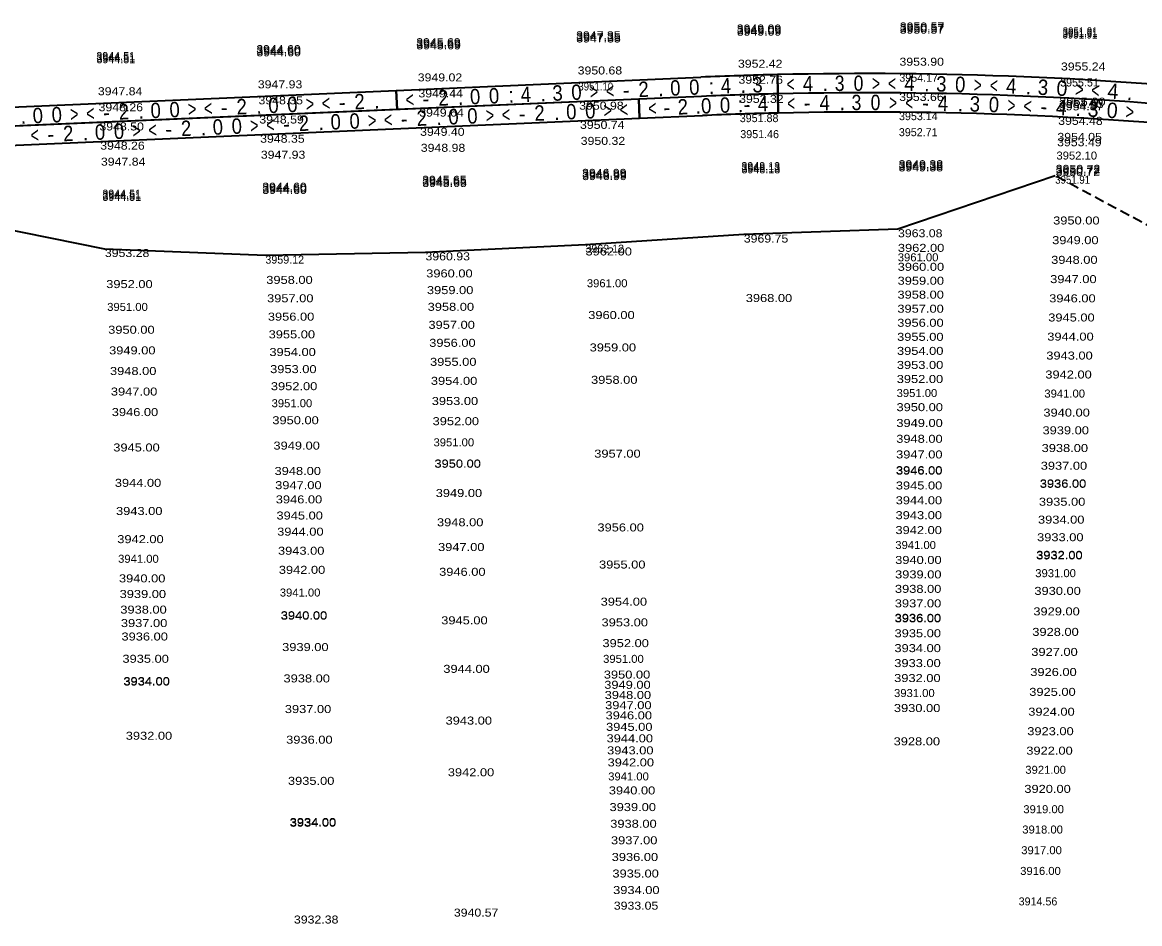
# Model space of a CAD drawing. Extents: x 49942 to 56479, y 47140 to 53283.
# Drawn here: x 53343 to 54041, y 49300 to 49863 of the extents above; entities that cross this region are included whole.
import ezdxf
from ezdxf.enums import TextEntityAlignment as Align

# ---------------------------------------------------------------- set-up
doc = ezdxf.new("R2010")
doc.units = 0
doc.header["$LTSCALE"] = 2
doc.linetypes.add('MEDIUM_DASHED', pattern=[4.5, 3, -1.5])
doc.layers.add('29', color=7, linetype='Continuous')
doc.layers.add('59', color=7, linetype='Continuous', lineweight=35)
doc.layers.add('63', color=7, linetype='Continuous', lineweight=35)

msp = doc.modelspace()

# ---------------------------------------------------------------- linework, layer by layer
at = {"layer": '59'}
for p, q in [((53988.534, 49767.027), (53890.322, 49733.603)), ((53394.861, 49721.266), (53293.897, 49741.36)), ((53890.322, 49733.603), (53793.986, 49730.281)), ((53695.025, 49723.963), (53595.139, 49719.179)), ((53793.986, 49730.281), (53695.025, 49723.963)), ((53495.134, 49717.131), (53394.861, 49721.266)), ((53595.139, 49719.179), (53495.134, 49717.131))]:
    msp.add_line(p, q, dxfattribs=at)
at = {"layer": '59', "linetype": 'MEDIUM_DASHED'}
msp.add_line((54082.2, 49716.709), (53988.534, 49767.027), dxfattribs=at)
at = {"layer": '63'}
for p, q in [((53576.866, 49820.33), (53767.149, 49828.569)), ((53814.981, 49830.161), (53815.26, 49818.164)), ((53815.26, 49818.164), (53814.981, 49830.161)), ((53815.539, 49806.167), (53815.26, 49818.164)), ((53815.26, 49818.164), (53815.539, 49806.167)), ((53728.923, 49802.891), (53768.187, 49804.591))]:
    msp.add_line(p, q, dxfattribs=at)
for points in [[(52494.091, 49773.45), (53576.866, 49820.33), (53577.385, 49808.342), (52494.61, 49761.461)], [(52680.665, 49757.505), (53728.923, 49802.891), (53728.404, 49814.88), (52680.146, 49769.494)]]:
    msp.add_lwpolyline(points, close=True, dxfattribs=at)
for points in [[(53767.668, 49816.58), (53577.385, 49808.342), (53576.866, 49820.33)], [(53767.668, 49816.58), (53728.404, 49814.88), (53728.923, 49802.891)]]:
    msp.add_lwpolyline(points, dxfattribs=at)
for radius, start, end in [(2391.064, 91.33234, 92.47917), (2391.064, 76.58708, 91.33234), (2379.064, 91.33234, 92.47917), (2379.064, 91.33234, 92.47917), (2379.064, 76.58708, 91.33234), (2379.064, 76.58708, 91.33234), (2367.064, 91.33234, 92.47917), (2367.064, 76.58708, 91.33234)]:
    msp.add_arc((53870.577, 47439.743), radius, start, end, dxfattribs=at)

# ---------------------------------------------------------------- texts
at = {"layer": '29'}
for s, width, p in [('3947.35', 1.15, (53689.256, 49852.226)), ('3949.09', 1.15, (53789.599, 49856.453)), ('3949.09', 1.15, (53789.633, 49855.454)), ('3949.09', 1.15, (53789.666, 49854.454)), ('3950.57', 1.15, (53891.416, 49855.717)), ('3950.57', 1.15, (53891.425, 49856.717)), ('3950.57', 1.15, (53891.434, 49857.717)), ('3951.91', 0.9, (53993.13, 49852.703)), ('3951.91', 0.9, (53993.18, 49853.702)), ('3951.91', 0.9, (53993.231, 49854.7)), ('3945.69', 1.15, (53589.349, 49847.901)), ('3945.69', 1.15, (53589.393, 49846.902)), ('3945.69', 1.15, (53589.436, 49845.903)), ('3947.35', 1.15, (53689.299, 49851.227)), ('3947.35', 1.15, (53689.342, 49850.228)), ('3944.60', 1.15, (53489.443, 49843.575)), ('3944.60', 1.15, (53489.486, 49842.576)), ('3944.60', 1.15, (53489.529, 49841.577)), ('3952.42', 1.15, (53790.335, 49834.466)), ('3953.90', 1.15, (53891.244, 49835.718)), ('3955.24', 1.15, (53992.117, 49832.729)), ('3949.02', 1.15, (53590.301, 49825.921)), ('3950.68', 1.15, (53690.207, 49830.247)), ('3952.76', 1.15, (53790.669, 49824.471)), ('3947.84', 1.15, (53390.488, 49817.27)), ('3947.93', 1.15, (53490.395, 49821.596)), ('3951.10', 0.9, (53690.64, 49820.256)), ('3948.35', 1.15, (53490.827, 49811.605)), ('3949.44', 1.15, (53590.733, 49815.931)), ('3952.32', 1.15, (53791.07, 49812.478)), ('3953.66', 1.15, (53891.055, 49813.719)), ('3955.00', 1.2, (53991.004, 49810.757)), ('3948.26', 1.15, (53390.921, 49807.279)), ('3949.64', 1.15, (53591.253, 49803.942)), ('3950.98', 1.15, (53691.159, 49808.267)), ('3954.87', 1.15, (53990.855, 49807.815)), ('3954.93', 1.15, (53990.929, 49809.286)), ('3948.59', 1.15, (53491.346, 49799.616)), ('3950.74', 1.15, (53691.678, 49796.279)), ('3954.48', 1.15, (53990.396, 49798.772)), ('3948.50', 1.15, (53391.44, 49795.291)), ('3949.40', 1.15, (53591.772, 49791.953)), ('3954.05', 1.15, (53989.89, 49788.785)), ('3948.26', 1.15, (53391.959, 49783.302)), ('3948.35', 1.15, (53491.865, 49787.627)), ('3948.98', 1.15, (53592.204, 49781.963)), ('3950.32', 1.15, (53692.111, 49786.288)), ('3953.49', 1.15, (53989.719, 49785.415)), ('3947.93', 1.15, (53492.298, 49777.637)), ('3952.10', 1.05, (53989.298, 49777.113)), ('3947.84', 1.15, (53392.391, 49773.311)), ('3949.38', 1.15, (53890.676, 49769.72)), ('3949.38', 1.15, (53890.685, 49770.72)), ('3949.38', 1.15, (53890.693, 49771.72)), ('3950.72', 1.15, (53988.827, 49767.812)), ('3950.72', 1.15, (53988.878, 49768.811)), ('3945.65', 1.15, (53593.069, 49761.981)), ('3945.65', 1.15, (53593.112, 49760.982)), ('3946.99', 1.15, (53692.976, 49766.307)), ('3946.99', 1.15, (53693.019, 49765.308)), ('3946.99', 1.15, (53693.062, 49764.309)), ('3951.91', 0.9, (53988.534, 49762.027)), ('3950.72', 1.15, (53988.776, 49766.813)), ('3944.60', 1.15, (53493.163, 49757.656)), ('3944.60', 1.15, (53493.206, 49756.657)), ('3944.60', 1.15, (53493.249, 49755.657)), ('3945.65', 1.15, (53593.156, 49759.983)), ('3950.00', 1.2, (53987.244, 49736.577)), ('3963.08', 1.15, (53890.322, 49728.603)), ('3969.75', 1.15, (53793.986, 49725.282)), ('3962.00', 1.2, (53890.244, 49719.477)), ('3949.00', 1.2, (53986.621, 49724.288)), ('3953.28', 1.15, (53394.861, 49716.266)), ('3960.93', 1.15, (53595.139, 49714.179)), ('3962.00', 1.2, (53695.1, 49717.235)), ('3961.00', 1.05, (53890.193, 49713.579)), ('3948.00', 1.2, (53985.998, 49711.998)), ('3960.00', 1.2, (53890.142, 49707.647)), ('3958.00', 1.2, (53495.682, 49699.472)), ('3960.00', 1.2, (53595.6, 49703.531)), ('3959.00', 1.2, (53890.067, 49698.961)), ('3947.00', 1.2, (53985.389, 49699.975)), ('3952.00', 1.2, (53395.701, 49696.867)), ('3959.00', 1.2, (53596.051, 49693.103)), ('3961.00', 1.05, (53695.96, 49697.385)), ('3957.00', 1.2, (53496.179, 49688.002)), ('3968.00', 1.2, (53795.227, 49688.15)), ('3958.00', 1.2, (53889.992, 49690.275)), ('3946.00', 1.2, (53984.779, 49687.953)), ('3951.00', 1.05, (53396.319, 49682.608)), ('3958.00', 1.2, (53596.503, 49682.675)), ('3960.00', 1.2, (53696.819, 49677.535)), ('3957.00', 1.2, (53889.917, 49681.491)), ('3956.00', 1.2, (53496.675, 49676.531)), ('3957.00', 1.2, (53596.99, 49671.43)), ('3956.00', 1.2, (53889.841, 49672.708)), ('3945.00', 1.2, (53984.174, 49676.01)), ('3950.00', 1.2, (53396.936, 49668.349)), ('3955.00', 1.2, (53497.154, 49665.484)), ('3955.00', 1.2, (53889.766, 49663.928)), ('3944.00', 1.2, (53983.569, 49664.068)), ('3956.00', 1.2, (53597.477, 49660.185)), ('3959.00', 1.2, (53697.695, 49657.307)), ('3949.00', 1.2, (53397.494, 49655.469)), ('3954.00', 1.2, (53497.632, 49654.438)), ('3954.00', 1.2, (53889.69, 49655.147)), ('3943.00', 1.2, (53982.969, 49652.234)), ('3948.00', 1.2, (53398.051, 49642.59)), ('3953.00', 1.2, (53498.094, 49643.77)), ('3955.00', 1.2, (53597.991, 49648.317)), ('3953.00', 1.2, (53889.614, 49646.378)), ('3954.00', 1.2, (53598.504, 49636.449)), ('3958.00', 1.2, (53698.571, 49637.08)), ('3952.00', 1.2, (53889.539, 49637.608)), ('3942.00', 1.2, (53982.369, 49640.399)), ('3947.00', 1.2, (53398.606, 49629.764)), ('3952.00', 1.2, (53498.556, 49633.101)), ('3951.00', 1.05, (53889.463, 49628.833)), ('3941.00', 1.05, (53981.767, 49628.512)), ('3951.00', 1.05, (53499.016, 49622.474)), ('3953.00', 1.2, (53599.05, 49623.856)), ('3946.00', 1.2, (53399.162, 49616.939)), ('3950.00', 1.2, (53889.387, 49620.008)), ('3940.00', 1.2, (53981.164, 49616.624)), ('3950.00', 1.2, (53499.476, 49611.847)), ('3952.00', 1.2, (53599.595, 49611.262)), ('3949.00', 1.2, (53889.302, 49610.133)), ('3948.00', 1.2, (53889.217, 49600.259)), ('3939.00', 1.2, (53980.603, 49605.551)), ('3945.00', 1.2, (53400.118, 49594.849)), ('3949.00', 1.2, (53500.162, 49596.01)), ('3951.00', 1.05, (53600.167, 49598.053)), ('3938.00', 1.2, (53980.042, 49594.478)), ('3957.00', 1.2, (53700.566, 49590.994)), ('3947.00', 1.2, (53889.133, 49590.494)), ('3948.00', 1.2, (53500.847, 49580.173)), ('3950.00', 1.2, (53600.739, 49584.844)), ('3950.00', 1.2, (53600.742, 49584.761)), ('3950.00', 1.2, (53600.747, 49584.664)), ('3946.00', 1.2, (53889.046, 49580.363)), ('3946.00', 1.2, (53889.048, 49580.527)), ('3946.00', 1.2, (53889.049, 49580.691)), ('3937.00', 1.2, (53979.483, 49583.445)), ('3944.00', 1.2, (53401.075, 49572.758)), ('3936.00', 1.2, (53978.916, 49572.275)), ('3936.00', 1.2, (53978.923, 49572.413)), ('3947.00', 1.2, (53501.231, 49571.301)), ('3949.00', 1.2, (53601.537, 49566.398)), ('3945.00', 1.2, (53888.967, 49571.116)), ('3936.00', 1.2, (53978.909, 49572.133)), ('3946.00', 1.2, (53501.616, 49562.428)), ('3944.00', 1.2, (53888.887, 49561.868)), ('3935.00', 1.2, (53978.343, 49560.96)), ('3943.00', 1.2, (53401.836, 49555.176)), ('3945.00', 1.2, (53502.052, 49552.355)), ('3943.00', 1.2, (53888.807, 49552.565)), ('3948.00', 1.2, (53602.328, 49548.133)), ('3956.00', 1.2, (53702.562, 49544.907)), ('3934.00', 1.2, (53977.776, 49549.786)), ('3942.00', 1.2, (53402.597, 49537.594)), ('3944.00', 1.2, (53502.488, 49542.282)), ('3942.00', 1.2, (53888.727, 49543.262)), ('3933.00', 1.2, (53977.219, 49538.794)), ('3943.00', 1.2, (53503.004, 49530.359)), ('3947.00', 1.2, (53602.998, 49532.669)), ('3941.00', 1.05, (53888.647, 49533.936)), ('3941.00', 1.05, (53403.128, 49525.344)), ('3940.00', 1.2, (53888.566, 49524.61)), ('3932.00', 1.2, (53976.643, 49527.425)), ('3932.00', 1.2, (53976.653, 49527.623)), ('3932.00', 1.2, (53976.662, 49527.802)), ('3942.00', 1.2, (53503.52, 49518.437)), ('3946.00', 1.2, (53603.667, 49517.204)), ('3955.00', 1.2, (53703.565, 49521.743)), ('3931.00', 1.05, (53976.082, 49516.355)), ('3940.00', 1.2, (53403.658, 49513.093)), ('3939.00', 1.2, (53888.488, 49515.583)), ('3939.00', 1.2, (53404.08, 49503.345)), ('3941.00', 1.05, (53504.134, 49504.269)), ('3938.00', 1.2, (53888.411, 49506.555)), ('3930.00', 1.2, (53975.521, 49505.285)), ('3954.00', 1.2, (53704.567, 49498.577)), ('3937.00', 1.2, (53888.333, 49497.514)), ('3938.00', 1.2, (53404.502, 49493.597)), ('3940.00', 1.2, (53504.747, 49490.101)), ('3940.00', 1.2, (53504.752, 49489.98)), ('3940.00', 1.2, (53504.761, 49489.789)), ('3936.00', 1.2, (53888.255, 49488.472)), ('3929.00', 1.2, (53974.872, 49492.489)), ('3937.00', 1.2, (53404.866, 49485.198)), ('3945.00', 1.2, (53604.979, 49486.903)), ('3953.00', 1.2, (53705.128, 49485.62)), ('3936.00', 1.2, (53888.252, 49488.123)), ('3936.00', 1.2, (53888.254, 49488.3)), ('3936.00', 1.2, (53405.229, 49476.798)), ('3935.00', 1.2, (53888.172, 49478.839)), ('3928.00', 1.2, (53974.224, 49479.694)), ('3939.00', 1.2, (53505.608, 49470.21)), ('3952.00', 1.2, (53705.689, 49472.663)), ('3934.00', 1.2, (53888.092, 49469.554)), ('3935.00', 1.2, (53405.831, 49462.896)), ('3951.00', 1.05, (53706.114, 49462.849)), ('3927.00', 1.2, (53973.59, 49467.185)), ('3944.00', 1.2, (53606.291, 49456.601)), ('3933.00', 1.2, (53888.012, 49460.207)), ('3926.00', 1.2, (53972.954, 49454.633)), ('3934.00', 1.2, (53406.433, 49448.995)), ('3934.00', 1.2, (53406.441, 49448.825)), ('3934.00', 1.2, (53406.448, 49448.655)), ('3938.00', 1.2, (53506.456, 49450.631)), ('3950.00', 1.2, (53706.539, 49453.035)), ('3949.00', 1.2, (53706.815, 49446.665)), ('3932.00', 1.2, (53887.931, 49450.861)), ('3948.00', 1.2, (53707.091, 49440.295)), ('3931.00', 1.05, (53887.851, 49441.497)), ('3925.00', 1.2, (53972.325, 49442.238)), ('3947.00', 1.2, (53707.366, 49433.931)), ('3937.00', 1.2, (53507.284, 49431.499)), ('3946.00', 1.2, (53707.642, 49427.566)), ('3930.00', 1.2, (53887.77, 49432.132)), ('3924.00', 1.2, (53971.697, 49429.843)), ('3943.00', 1.2, (53607.689, 49424.316)), ('3945.00', 1.2, (53707.953, 49420.395)), ('3932.00', 1.2, (53407.912, 49414.832)), ('3936.00', 1.2, (53508.113, 49412.368)), ('3944.00', 1.2, (53708.263, 49413.224)), ('3923.00', 1.2, (53971.081, 49417.679)), ('3943.00', 1.2, (53708.588, 49405.709)), ('3928.00', 1.2, (53887.591, 49411.347)), ('3922.00', 1.2, (53970.464, 49405.515)), ('3942.00', 1.2, (53708.914, 49398.194)), ('3942.00', 1.2, (53609.087, 49392.031)), ('3921.00', 1.05, (53969.86, 49393.586)), ('3935.00', 1.2, (53509.225, 49386.682)), ('3941.00', 1.05, (53709.293, 49389.443)), ('3940.00', 1.2, (53709.671, 49380.693)), ('3920.00', 1.2, (53969.255, 49381.657)), ('3939.00', 1.2, (53710.122, 49370.292)), ('3919.00', 1.05, (53968.612, 49368.967)), ('3934.00', 1.2, (53510.337, 49360.997)), ('3934.00', 1.2, (53510.346, 49360.795)), ('3934.00', 1.2, (53510.358, 49360.509)), ('3938.00', 1.2, (53710.572, 49359.89)), ('3918.00', 1.05, (53967.969, 49356.278)), ('3937.00', 1.2, (53711.019, 49349.559)), ('3917.00', 1.05, (53967.314, 49343.357)), ('3936.00', 1.2, (53711.471, 49339.132)), ('3935.00', 1.2, (53711.918, 49328.81)), ('3916.00', 1.05, (53966.659, 49330.436)), ('3934.00', 1.2, (53712.365, 49318.489)), ('3933.05', 1.15, (53712.787, 49308.736)), ('3932.38', 1.15, (53512.974, 49300.084)), ('3940.57', 1.15, (53612.881, 49304.41))]:
    msp.add_text(s, height=5, dxfattribs=dict(at, width=width)).set_placement(p)
for s, p in [('3944.51', (53389.536, 49839.249)), ('3944.51', (53389.58, 49838.25)), ('3944.51', (53389.623, 49837.251)), ('3954.17', (53891.158, 49825.718)), ('3955.51', (53991.611, 49822.741)), ('3951.88', (53791.471, 49800.485)), ('3953.14', (53890.952, 49801.719)), ('3951.46', (53791.805, 49790.49)), ('3952.71', (53890.866, 49791.719)), ('3948.13', (53792.474, 49770.501)), ('3948.13', (53792.507, 49769.502)), ('3948.13', (53792.54, 49768.502)), ('3944.51', (53393.256, 49753.33)), ('3944.51', (53393.3, 49752.331)), ('3944.51', (53393.343, 49751.332)), ('3962.12', (53695.025, 49718.963)), ('3959.12', (53495.134, 49712.131)), ('3914.56', (53965.694, 49311.398))]:
    msp.add_text(s, height=5, dxfattribs=at).set_placement(p)
at = {"layer": '63'}
for s, rotation, width, p in [('3', 1.638, 0.9, (53802.694, 49819.035)), ('4', 0.878, 0.9, (53834.185, 49819.726)), ('3', 0.402, 0.85, (53853.897, 49819.945)), ('0', 0.119, 0.85, (53865.662, 49819.999)), ('4', 359.353, 0.9, (53897.498, 49819.852)), ('3', 358.878, 0.9, (53917.289, 49819.545)), ('0', 358.594, 0.9, (53929.098, 49819.284)), ('0', 2.479, 0.9, (53638.185, 49812.175)), ('4', 2.479, 0.9, (53658.009, 49813.033)), ('3', 2.479, 0.9, (53677.833, 49813.892)), ('0', 2.479, 0.9, (53689.664, 49814.404)), ('>', 2.479, 0.7, (53700.599, 49814.877)), ('<', 2.479, 0.7, (53710.637, 49815.312)), ('2', 2.479, 0.9, (53731.609, 49816.22)), ('0', 2.479, 0.9, (53751.433, 49817.078)), ('0', 2.479, 0.9, (53763.265, 49817.591)), ('4', 2.113, 0.9, (53782.991, 49818.392)), ('<', 1.14, 0.65, (53823.313, 49819.536)), ('>', 359.856, 0.65, (53876.559, 49819.998)), ('<', 359.616, 0.65, (53886.581, 49819.951)), ('>', 358.332, 0.65, (53940.012, 49818.992)), ('<', 358.091, 0.65, (53950.029, 49818.679)), ('4', 357.829, 0.9, (53960.939, 49818.288)), ('3', 357.353, 0.9, (53980.715, 49817.454)), ('0', 357.069, 0.95, (53992.514, 49816.878)), ('>', 356.807, 0.7, (54003.415, 49816.295)), ('<', 356.566, 0.7, (54013.421, 49815.715)), ('4', 356.304, 0.95, (54024.317, 49815.034)), ('2', 2.479, 0.9, (53480.559, 49805.35)), ('0', 2.479, 0.9, (53500.383, 49806.209)), ('0', 2.479, 0.9, (53512.214, 49806.721)), ('>', 2.479, 0.7, (53523.149, 49807.194)), ('<', 2.479, 0.7, (53533.186, 49807.629)), ('2', 2.479, 0.9, (53554.159, 49808.537)), ('<', 2.479, 0.7, (53585.557, 49809.897)), ('2', 2.479, 0.9, (53606.53, 49810.805)), ('0', 2.479, 0.9, (53626.354, 49811.663)), ('2', 2.479, 0.9, (53756.116, 49805.27)), ('0', 2.403, 0.9, (53770.697, 49805.897)), ('0', 2.137, 0.9, (53782.434, 49806.363)), ('4', 1.564, 0.9, (53806.055, 49807.125)), ('<', 1.138, 0.65, (53823.632, 49807.54)), ('4', 0.63, 0.9, (53844.59, 49807.861)), ('3', 0.15, 0.85, (53864.402, 49807.996)), ('0', 359.863, 0.85, (53876.249, 49807.997)), ('>', 359.598, 0.65, (53887.222, 49807.946)), ('<', 359.355, 0.65, (53897.294, 49807.854)), ('4', 358.847, 0.9, (53918.337, 49807.522)), ('3', 358.367, 0.9, (53938.224, 49807.037)), ('0', 358.08, 0.9, (53950.09, 49806.668)), ('0', 2.479, 0.9, (53353.182, 49799.835)), ('0', 2.479, 0.9, (53365.013, 49800.348)), ('>', 2.479, 0.7, (53375.948, 49800.821)), ('<', 2.479, 0.7, (53385.986, 49801.256)), ('2', 2.479, 0.9, (53406.958, 49802.164)), ('0', 2.479, 0.9, (53426.782, 49803.022)), ('0', 2.479, 0.9, (53438.614, 49803.534)), ('>', 2.479, 0.7, (53449.548, 49804.008)), ('<', 2.479, 0.7, (53459.586, 49804.442)), ('2', 2.479, 0.9, (53593.013, 49798.208)), ('0', 2.479, 0.9, (53612.837, 49799.066)), ('0', 2.479, 0.9, (53624.669, 49799.579)), ('>', 2.479, 0.7, (53635.604, 49800.052)), ('<', 2.479, 0.7, (53645.641, 49800.487)), ('2', 2.479, 0.9, (53666.614, 49801.395)), ('0', 2.479, 0.9, (53686.438, 49802.253)), ('0', 2.479, 0.9, (53698.269, 49802.765)), ('>', 2.479, 0.7, (53709.204, 49803.239)), ('<', 2.479, 0.7, (53719.242, 49803.673)), ('<', 2.479, 0.7, (53737.095, 49804.446)), ('>', 357.815, 0.65, (53961.056, 49806.276)), ('<', 357.572, 0.7, (53971.12, 49805.87)), ('4', 357.064, 0.95, (53992.143, 49804.882)), ('3', 356.583, 0.95, (54012.005, 49803.777)), ('0', 356.297, 0.95, (54023.854, 49803.038)), ('>', 356.032, 0.7, (54034.802, 49802.304)), ('2', 2.479, 0.9, (53445.813, 49791.835)), ('0', 2.479, 0.9, (53465.637, 49792.693)), ('0', 2.479, 0.9, (53477.468, 49793.205)), ('>', 2.479, 0.7, (53488.403, 49793.679)), ('<', 2.479, 0.7, (53498.441, 49794.113)), ('2', 2.479, 0.9, (53519.413, 49795.021)), ('0', 2.479, 0.9, (53539.237, 49795.88)), ('0', 2.479, 0.9, (53551.069, 49796.392)), ('>', 2.479, 0.7, (53562.003, 49796.865)), ('<', 2.479, 0.7, (53572.041, 49797.3)), ('<', 2.479, 0.7, (53351.24, 49787.74)), ('2', 2.479, 0.9, (53372.212, 49788.648)), ('0', 2.479, 0.9, (53392.036, 49789.506)), ('0', 2.479, 0.9, (53403.868, 49790.019)), ('>', 2.479, 0.7, (53414.803, 49790.492)), ('<', 2.479, 0.7, (53424.84, 49790.927))]:
    msp.add_text(s, height=9.6, rotation=rotation, dxfattribs=dict(at, width=width)).set_placement(p, align=Align.CENTER)
for s, rotation, p in [(':', 2.351, (53773.956, 49818.044)), ('-', 2.479, (53595.595, 49810.331)), (':', 2.479, (53648.9, 49812.639)), ('.', 2.479, (53668.724, 49813.497)), ('-', 2.479, (53720.675, 49815.747)), ('.', 2.479, (53742.325, 49816.684)), ('.', 1.875, (53793.696, 49818.764)), ('.', 0.64, (53844.999, 49819.869)), ('.', 359.116, (53908.331, 49819.707)), ('.', 357.591, (53971.637, 49817.86)), ('.', 356.066, (54034.872, 49814.329)), ('-', 2.479, (53469.624, 49804.877)), ('-', 2.479, (53543.224, 49808.064)), ('.', 2.479, (53564.874, 49809.001)), ('.', 2.479, (53617.245, 49811.268)), ('-', 2.479, (53746.157, 49804.839)), (':', 1.925, (53792.053, 49806.705)), ('-', 1.806, (53796.106, 49806.834)), ('-', 0.895, (53833.663, 49807.717)), ('.', 0.39, (53855.475, 49807.958)), ('-', 359.112, (53907.366, 49807.719)), ('.', 358.607, (53929.175, 49807.281)), ('-', 357.329, (53981.183, 49805.421)), ('.', 2.479, (53344.073, 49799.441)), ('-', 2.479, (53396.024, 49801.69)), ('.', 2.479, (53417.673, 49802.628)), ('.', 2.479, (53491.274, 49805.814)), ('-', 2.479, (53582.079, 49797.735)), ('-', 2.479, (53655.679, 49800.921)), ('.', 2.479, (53677.329, 49801.859)), ('.', 2.479, (53765.699, 49805.685)), ('.', 356.823, (54002.819, 49804.311)), ('-', 2.479, (53434.878, 49791.361)), ('.', 2.479, (53456.528, 49792.299)), ('-', 2.479, (53508.479, 49794.548)), ('.', 2.479, (53530.128, 49795.485)), ('.', 2.479, (53603.729, 49798.672)), ('-', 2.479, (53361.278, 49788.175)), ('.', 2.479, (53382.928, 49789.112))]:
    msp.add_text(s, height=9.6, rotation=rotation, dxfattribs=at).set_placement(p, align=Align.CENTER)

doc.saveas('drawing.dxf')
